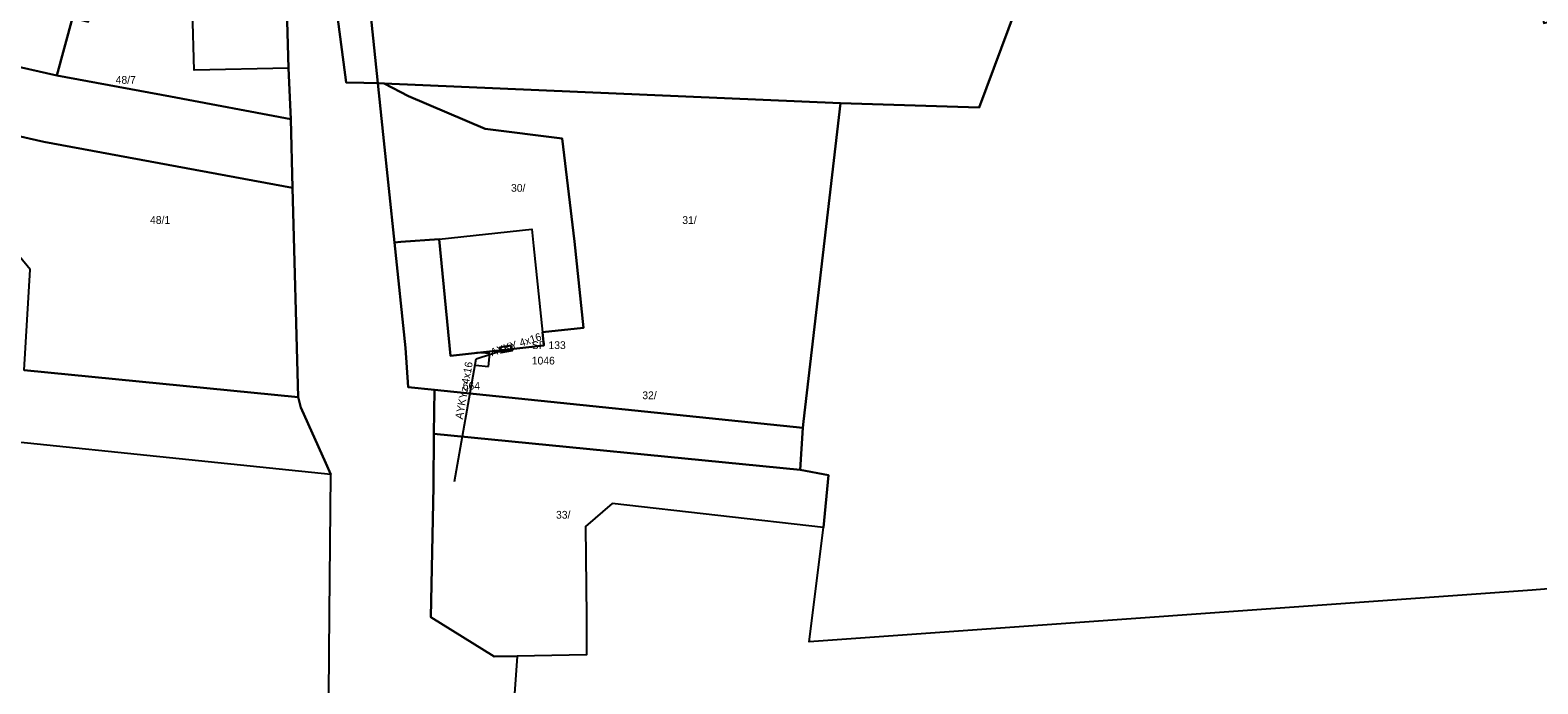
# Model space of a CAD drawing. Extents: x -793400 to -756198, y -1074141 to -1042963.
# Drawn here: x -783393.1 to -783247, y -1065417.9 to -1065354.6 of the extents above; entities that cross this region are included whole.
import ezdxf

# ---------------------------------------------------------------- set-up
doc = ezdxf.new("R2010")
doc.units = 0
for name, color, linetype in [('Parcela', 7, 'Continuous'), ('PB nn', 7, 'Continuous'), ('Popiskový text - Parcela', 7, 'Continuous'), ('Popiskový text - PB nn - sk_2 - SJZ', 7, 'Continuous'), ('Popiskový text - Přípojková skříň nn - SJZ', 7, 'Continuous'), ('Popiskový text - Přípojková skříň nn - Typ', 7, 'Continuous'), ('Popiskový text - Vedení nn svod', 7, 'Continuous'), ('Popiskový text - Vedení nn venkovní izol', 7, 'Continuous'), ('Skříň', 7, 'Continuous'), ('Spojnice nn', 7, 'Continuous'), ('Stavební objekt', 7, 'Continuous'), ('Vedení nn svod', 7, 'Continuous'), ('Vedení nn venkovní izolované', 7, 'Continuous')]:
    doc.layers.add(name, color=color, linetype=linetype)

msp = doc.modelspace()

# ---------------------------------------------------------------- linework, layer by layer
at = {"layer": 'Parcela'}
for points in [[(-783361.83, -1065336.05), (-783359.37, -1065359.72), (-783360.74, -1065359.7), (-783362.44, -1065359.67), (-783365.91, -1065333.11), (-783353.85, -1065326.26), (-783331.79, -1065317.39), (-783361.23, -1065335.68)], [(-783291.97, -1065337.56), (-783284.45, -1065347.4), (-783273.57, -1065347.14), (-783271.05, -1065346.73), (-783255.53, -1065352.15), (-783254.94, -1065352.03), (-783247.05, -1065350.51), (-783246.4, -1065353.9), (-783185.97, -1065339.08), (-783185.2, -1065338.9), (-783177.15, -1065384.24), (-783173.84, -1065402.95), (-783217.4, -1065406.42), (-783247.51, -1065408.83), (-783317.57, -1065413.84), (-783316.17, -1065402.75), (-783315.7, -1065397.69), (-783318.45, -1065397.17), (-783318.2, -1065393.1), (-783318.13, -1065392.5), (-783314.55, -1065361.66), (-783301.1, -1065362.07)], [(-783385.26, -1065345.04), (-783387.42, -1065353.77), (-783388.96, -1065353.38), (-783390.46, -1065358.99), (-783399.05, -1065357.05), (-783405.47, -1065355.39), (-783401.77, -1065341.01), (-783401.01, -1065341.48), (-783388.29, -1065344.35)], [(-783368.29, -1065349.1), (-783368.03, -1065358.26), (-783367.8, -1065363.21), (-783379.46, -1065361.02), (-783390.46, -1065358.99), (-783388.96, -1065353.38), (-783387.42, -1065353.77), (-783385.26, -1065345.04), (-783382.09, -1065345.81), (-783379.41, -1065346.47), (-783377.5, -1065346.94)], [(-783367.8, -1065363.21), (-783367.63, -1065369.85), (-783391.74, -1065365.41), (-783400.14, -1065363.49), (-783407.53, -1065361.56), (-783405.91, -1065355.28), (-783405.47, -1065355.39), (-783399.05, -1065357.05), (-783390.46, -1065358.99), (-783379.46, -1065361.02)], [(-783341.5, -1065365.07), (-783340.31, -1065375.06), (-783339.45, -1065383.41), (-783343.42, -1065383.85), (-783343.29, -1065385.14), (-783352.33, -1065386.12), (-783353.44, -1065374.83), (-783357.15, -1065375.1), (-783357.74, -1065375.17), (-783358.84, -1065364.7), (-783359.37, -1065359.72), (-783358.76, -1065359.74), (-783356.38, -1065360.97), (-783348.97, -1065364.16)], [(-783314.55, -1065361.66), (-783318.13, -1065392.5), (-783318.2, -1065393.1), (-783353.87, -1065389.42), (-783356.43, -1065389.16), (-783356.68, -1065385.36), (-783357.74, -1065375.17), (-783357.15, -1065375.1), (-783353.44, -1065374.83), (-783352.33, -1065386.12), (-783343.29, -1065385.14), (-783343.42, -1065383.85), (-783339.45, -1065383.41), (-783340.31, -1065375.06), (-783341.5, -1065365.07), (-783348.97, -1065364.16), (-783356.38, -1065360.97), (-783358.76, -1065359.74)], [(-783367.63, -1065369.85), (-783367.09, -1065390.13), (-783393.63, -1065387.51), (-783393.07, -1065377.76), (-783396.35, -1065373.81), (-783408.7, -1065366.12), (-783407.53, -1065361.56), (-783400.14, -1065363.49), (-783391.74, -1065365.41)], [(-783318.2, -1065393.1), (-783318.45, -1065397.17), (-783353.93, -1065393.69), (-783353.87, -1065389.42)], [(-783315.7, -1065397.69), (-783316.17, -1065402.75), (-783336.67, -1065400.44), (-783339.24, -1065402.66), (-783339.16, -1065411.41), (-783339.14, -1065415.1), (-783345.87, -1065415.21), (-783348.09, -1065415.25), (-783354.24, -1065411.43), (-783353.97, -1065398.78), (-783353.93, -1065393.69), (-783318.45, -1065397.17)]]:
    msp.add_lwpolyline(points, close=True, dxfattribs=at)
for points in [[(-783365.91, -1065333.11), (-783362.44, -1065359.67), (-783360.74, -1065359.7), (-783359.37, -1065359.72), (-783358.84, -1065364.7), (-783357.74, -1065375.17), (-783356.68, -1065385.36), (-783356.43, -1065389.16), (-783353.87, -1065389.42), (-783353.93, -1065393.69), (-783353.97, -1065398.78), (-783354.24, -1065411.43), (-783348.09, -1065415.25), (-783345.87, -1065415.21), (-783346.11, -1065418.88)], [(-783291.97, -1065337.56), (-783301.1, -1065362.07), (-783314.55, -1065361.66), (-783358.76, -1065359.74), (-783359.37, -1065359.72), (-783361.83, -1065336.05)], [(-783364.1, -1065418.92), (-783364.05, -1065411.1), (-783363.92, -1065397.64), (-783364.42, -1065396.53), (-783366.83, -1065391.14), (-783367.09, -1065390.13), (-783367.63, -1065369.85), (-783367.8, -1065363.21), (-783368.03, -1065358.26), (-783368.29, -1065349.1), (-783377.5, -1065346.94), (-783379.41, -1065346.47), (-783382.09, -1065345.81), (-783385.26, -1065345.04), (-783388.29, -1065344.35), (-783401.01, -1065341.48)], [(-783393.63, -1065387.51), (-783367.09, -1065390.13), (-783366.83, -1065391.14), (-783364.42, -1065396.53), (-783363.92, -1065397.64), (-783410.23, -1065392.84)]]:
    msp.add_lwpolyline(points, dxfattribs=at)
at = {"layer": 'PB nn'}
for p, q in [((-783348.53, -1065385.92), (-783349.78, -1065385.8)), ((-783348.66, -1065387.15), (-783348.53, -1065385.92)), ((-783349.9, -1065387.02), (-783348.66, -1065387.15))]:
    msp.add_line(p, q, dxfattribs=at)
at = {"layer": 'Skříň'}
for points in [[(-783347.55, -1065385.3), (-783346.45, -1065385.09), (-783346.35, -1065385.64), (-783347.45, -1065385.85)], [(-783346.49, -1065385.16), (-783347.49, -1065385.34), (-783347.41, -1065385.78), (-783346.41, -1065385.6)]]:
    msp.add_lwpolyline(points, close=True, dxfattribs=at)
at = {"layer": 'Spojnice nn'}
msp.add_line((-783351.94, -1065398.31), (-783349.84, -1065386.41), dxfattribs=at)
at = {"layer": 'Stavební objekt'}
for points in [[(-783368.03, -1065358.26), (-783377.17, -1065358.46), (-783377.5, -1065346.94), (-783368.29, -1065349.1)], [(-783343.29, -1065385.14), (-783352.33, -1065386.12), (-783353.44, -1065374.83), (-783344.46, -1065373.87), (-783344.29, -1065375.47), (-783343.42, -1065383.85)]]:
    msp.add_lwpolyline(points, close=True, dxfattribs=at)
at = {"layer": 'Vedení nn svod'}
msp.add_line((-783349.84, -1065386.41), (-783346.95, -1065385.47), dxfattribs=at)
at = {"layer": 'Vedení nn venkovní izolované'}
msp.add_line((-783351.94, -1065398.31), (-783349.84, -1065386.41), dxfattribs=at)

# ---------------------------------------------------------------- texts
at = {"layer": 'Popiskový text - Parcela'}
for s, p in [('48/7', (-783384.77, -1065359.78)), ('30/', (-783346.46, -1065370.24)), ('48/1', (-783381.44, -1065373.35)), ('31/', (-783329.87, -1065373.36)), ('32/', (-783333.74, -1065390.33)), ('33/', (-783342.1, -1065401.9))]:
    msp.add_text(s, height=0.75, dxfattribs=at).set_placement(p)
at = {"layer": 'Popiskový text - PB nn - sk_2 - SJZ'}
msp.add_text('664', height=0.75, dxfattribs=at).set_placement((-783351.14, -1065389.41))
at = {"layer": 'Popiskový text - Přípojková skříň nn - SJZ'}
msp.add_text('1046', height=0.75, dxfattribs=at).set_placement((-783344.45, -1065386.97))
at = {"layer": 'Popiskový text - Přípojková skříň nn - Typ'}
msp.add_text('SP 133', height=0.75, dxfattribs=at).set_placement((-783344.45, -1065385.47))
at = {"layer": 'Popiskový text - Vedení nn svod'}
msp.add_text('AYKY 4x16', height=0.75, rotation=17.9909, dxfattribs=at).set_placement((-783348.32, -1065386.18))
at = {"layer": 'Popiskový text - Vedení nn venkovní izol'}
msp.add_text('AYKYz 4x16', height=0.75, rotation=79.9849, dxfattribs=at).set_placement((-783351.14, -1065392.32))

doc.saveas('drawing.dxf')
